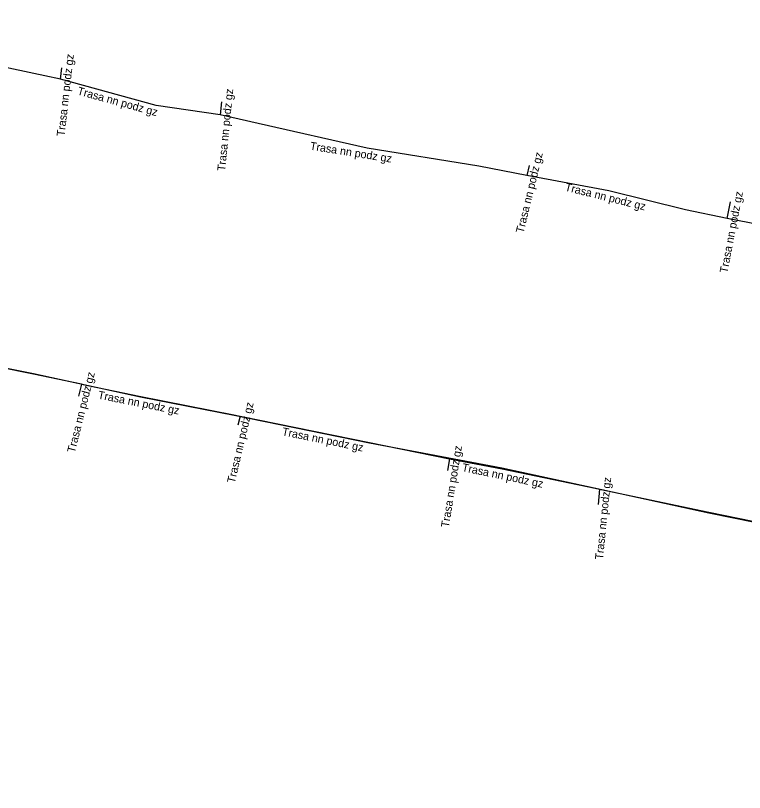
# Model space of a CAD drawing. Extents: x -687924 to -686708, y -1056742 to -1056249.
# Drawn here: x -687161.73 to -687116.22, y -1056514.95 to -1056466.44 of the extents above; entities that cross this region are included whole.
import ezdxf

# ---------------------------------------------------------------- set-up
doc = ezdxf.new("R2010")
doc.units = 0
for name, color, linetype in [('Popiskový text - Ostatní atributy Trasy', 7, 'Continuous'), ('Spojnice NN', 7, 'Continuous'), ('Spojnice VN', 7, 'Continuous')]:
    doc.layers.add(name, color=color, linetype=linetype)

msp = doc.modelspace()

# ---------------------------------------------------------------- linework, layer by layer
at = {"layer": 'Spojnice NN'}
for points in [[(-687158.92, -1056470.41), (-687164.82, -1056469.16), (-687173.07, -1056467.66), (-687177.81, -1056466.44)], [(-687158.92, -1056470.41), (-687158.84, -1056469.71)], [(-687148.95, -1056472.64), (-687152.96, -1056472.05), (-687158.92, -1056470.41)], [(-687148.87, -1056471.83), (-687148.95, -1056472.64)], [(-687129.81, -1056476.43), (-687132.81, -1056475.84), (-687139.77, -1056474.73), (-687146.58, -1056473.18), (-687148.95, -1056472.64)], [(-687129.66, -1056475.81), (-687129.81, -1056476.43)], [(-687117.29, -1056479.12), (-687119.9, -1056478.58), (-687124.68, -1056477.39), (-687129.81, -1056476.43)], [(-687117.29, -1056479.12), (-687117.09, -1056478.08)], [(-687103.4, -1056481.79), (-687104.94, -1056481.5), (-687117.29, -1056479.12)], [(-687157.622, -1056489.464), (-687160.615, -1056488.826), (-687166.818, -1056487.585), (-687178.657, -1056485.1), (-687188.89, -1056483.29)], [(-687157.622, -1056489.464), (-687157.81, -1056490.21)], [(-687157.622, -1056489.464), (-687154.01, -1056490.21), (-687148.11, -1056491.38), (-687147.718, -1056491.453)], [(-687147.718, -1056491.453), (-687147.85, -1056492.01)], [(-687147.718, -1056491.453), (-687139.637, -1056493.092), (-687134.642, -1056494.123)], [(-687134.642, -1056494.123), (-687134.76, -1056494.85)], [(-687134.642, -1056494.123), (-687131.345, -1056494.745), (-687125.552, -1056495.948), (-687125.265, -1056496.018)], [(-687125.265, -1056496.018), (-687125.361, -1056496.96)], [(-687125.265, -1056496.018), (-687118.435, -1056497.459), (-687108.378, -1056499.508), (-687107.231, -1056500.259), (-687104.669, -1056500.689), (-687103.31, -1056500.58), (-687097.395, -1056501.42), (-687094.57, -1056502.21)]]:
    msp.add_lwpolyline(points, dxfattribs=at)
at = {"layer": 'Spojnice VN'}
msp.add_lwpolyline([(-687166.79, -1056487.57), (-687160.61, -1056488.8), (-687153.93, -1056490.24), (-687148.09, -1056491.4), (-687139.64, -1056493.12), (-687131.37, -1056494.68), (-687125.6, -1056495.92), (-687118.44, -1056497.5), (-687108.39, -1056499.54), (-687107.25, -1056500.28), (-687104.67, -1056500.71), (-687103.36, -1056500.62), (-687097.35, -1056501.42), (-687088.7, -1056503.06), (-687086.31, -1056503.72), (-687079.86, -1056505.07), (-687074.02, -1056506.21), (-687066.23, -1056507.72), (-687060.66, -1056508.98), (-687056.66, -1056509.77), (-687044.93, -1056512.15), (-687038.62, -1056513.64), (-687031.75, -1056514.95)], dxfattribs=at)

# ---------------------------------------------------------------- texts
at = {"layer": 'Popiskový text - Ostatní atributy Trasy'}
for rotation, p in [(83.4802, (-687158.677, -1056474.002)), (344.6148, (-687157.912, -1056471.361)), (84.3595, (-687148.646, -1056476.173)), (350.9386, (-687143.376, -1056474.813)), (76.3995, (-687130.019, -1056480.057)), (346.0202, (-687127.465, -1056477.367)), (79.1145, (-687117.287, -1056482.547)), (75.8463, (-687158.038, -1056493.772)), (348.7835, (-687156.619, -1056490.355)), (76.6678, (-687148.05, -1056495.67)), (348.5371, (-687145.124, -1056492.642)), (80.7807, (-687134.683, -1056498.434)), (348.2718, (-687133.891, -1056494.88)), (84.181, (-687125.061, -1056500.429))]:
    msp.add_text('Trasa nn podz gz', height=0.5, rotation=rotation, dxfattribs=at).set_placement(p)

doc.saveas('drawing.dxf')
